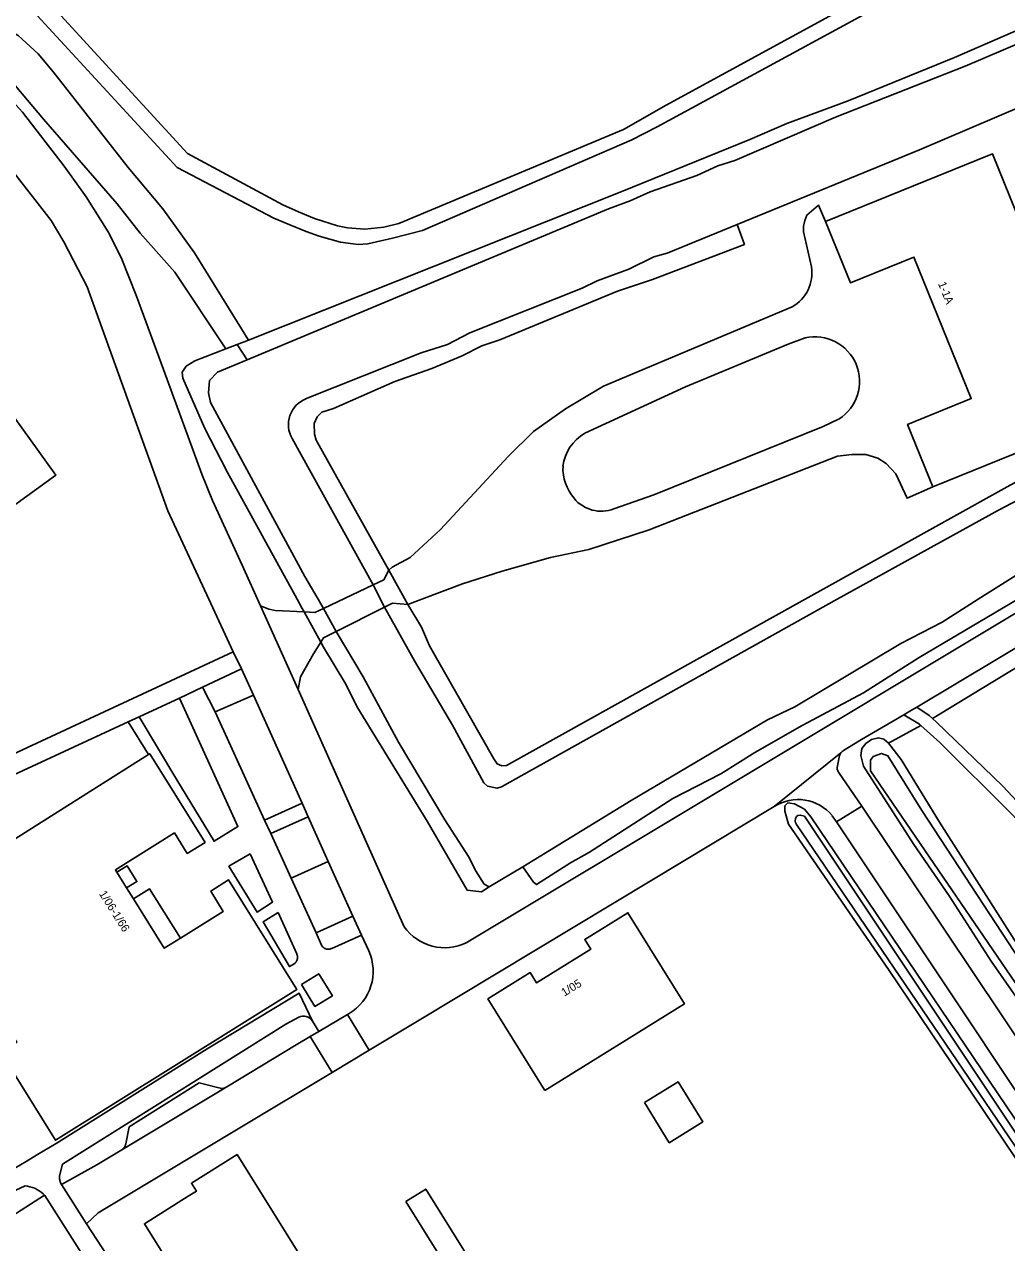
# Model space of a CAD drawing. Extents: x 162791 to 163827, y 385795 to 386523.
# Drawn here: x 163143.1 to 163263.1, y 386171.4 to 386320.2 of the extents above; entities that cross this region are included whole.
import ezdxf

# ---------------------------------------------------------------- set-up
doc = ezdxf.new("R2010")
doc.units = 0
for name, color, linetype in [('IMGEO_Dek', 7, 'Continuous'), ('IMGEO_Duiker', 7, 'Continuous'), ('IMGEO_Erf', 7, 'Continuous'), ('IMGEO_Gemengd_bos', 7, 'Continuous'), ('IMGEO_Groenvoorziening', 7, 'Continuous'), ('IMGEO_Pand', 7, 'Continuous'), ('IMGEO_Pand_nummerreeks', 7, 'Continuous'), ('IMGEO_Parkeervlak_halfverhard', 7, 'Continuous'), ('IMGEO_Parkeervlak_open', 7, 'Continuous'), ('IMGEO_Rijbaan_lokaal_gesloten', 7, 'Continuous'), ('IMGEO_Rijbaan_lokaal_onverhard', 7, 'Continuous'), ('IMGEO_Rijbaan_lokaal_open', 7, 'Continuous'), ('IMGEO_Voetpad_halfverhard', 7, 'Continuous'), ('IMGEO_Voetpad_open', 7, 'Continuous'), ('IMGEO_Waterloop', 7, 'Continuous'), ('IMGEO_Woonerf_gesloten', 7, 'Continuous'), ('IMGEO_Woonerf_open', 7, 'Continuous')]:
    doc.layers.add(name, color=color, linetype=linetype)

msp = doc.modelspace()

# ---------------------------------------------------------------- linework, layer by layer
at = {"layer": 'IMGEO_Dek'}
msp.add_lwpolyline([(163187.14, 386249.05), (163188.1, 386249.52), (163189.98, 386249.35), (163187.66, 386253.56), (163187.03, 386252.37), (163185.76, 386251.76), (163179.68, 386248.88), (163178.62, 386248.38), (163177.3, 386248.45), (163179.35, 386244.77), (163179.68, 386245.3), (163181.21, 386246.07)], close=True, dxfattribs=at)
at = {"layer": 'IMGEO_Duiker'}
msp.add_lwpolyline([(163170.35, 386279.25), (163169.11, 386281.15)], dxfattribs=at)
at = {"layer": 'IMGEO_Erf'}
for points in [[(163276.83, 386311.46), (163279.76, 386304.64), (163280.52, 386303.16), (163282.08, 386299.04), (163282.71, 386297.57), (163284.13, 386298.22), (163285.26, 386295.57), (163283.84, 386294.94), (163285.21, 386290.76), (163289.29, 386279.83), (163289.57, 386278.55), (163289.29, 386277.99), (163288.89, 386277.59), (163278.14, 386271.64), (163263.57, 386263.94), (163238.52, 386250), (163202.05, 386229.7), (163201.46, 386229.64), (163200.89, 386229.9), (163200.49, 386230.52), (163192.64, 386244.3), (163191.66, 386246.6), (163189.98, 386249.35)], [(163187.66, 386253.56), (163178.79, 386269.46), (163178.59, 386270.16), (163178.54, 386271.49), (163178.89, 386272.28), (163179.47, 386272.86), (163180.89, 386273.3), (163188.38, 386276.6), (163192.89, 386278.2), (163196.61, 386279.76), (163199.02, 386280.98), (163201.22, 386281.72), (163215.6, 386287.65), (163219.88, 386289.08), (163231.11, 386293.35), (163230.21, 386295.8)], [(163274.97, 386170.16), (163270.07, 386177.82), (163239.23, 386223.44), (163238.43, 386224.34), (163237.21, 386225.02), (163236.42, 386225.12), (163236.06, 386224.76), (163236.06, 386224.12), (163236.48, 386222.54), (163248.69, 386204.78), (163271.93, 386170.32)]]:
    msp.add_lwpolyline(points, dxfattribs=at)
at = {"layer": 'IMGEO_Gemengd_bos'}
for points in [[(163170.49, 386281.68), (163216.12, 386299.84), (163231.77, 386306.19), (163236.27, 386308.14), (163243.77, 386310.9), (163256.76, 386316.2), (163271.03, 386322.39), (163280.17, 386325.68), (163281.39, 386325.8), (163282.19, 386325.7), (163283.21, 386325.04), (163284.71, 386323.26), (163285.49, 386321.88), (163292.27, 386304.07), (163292.55, 386303.03), (163292.44, 386302.04), (163292.58, 386301.71)], [(163177.3, 386248.45), (163177.07, 386248.86), (163176.45, 386250), (163167.9, 386265.59), (163165.18, 386270.87), (163162.48, 386277.01), (163162.4, 386277.75), (163162.9, 386278.49), (163163.94, 386279.15), (163167.75, 386280.62)], [(163254.1, 386235.44), (163285.45, 386254.48)], [(163248.69, 386232.43), (163252.67, 386234.58)], [(163325.04, 386213.73), (163315.3, 386205.22), (163293.77, 386185.98), (163287.15, 386179.57), (163285.99, 386178.87), (163285.43, 386178.77), (163284.59, 386179.47), (163283.61, 386180.97), (163277.41, 386189.09), (163272.42, 386195.99), (163268.06, 386202.41), (163264.06, 386208.45), (163254.95, 386222.79), (163250.27, 386230.43), (163248.69, 386232.43)]]:
    msp.add_lwpolyline(points, dxfattribs=at)
at = {"layer": 'IMGEO_Groenvoorziening'}
for points in [[(163204.03, 386217.31), (163205.33, 386215.45), (163205.69, 386215.15), (163209.85, 386217.82), (163212.19, 386219.1), (163222.34, 386225.65), (163228.24, 386228.66), (163232.38, 386231.28), (163238.16, 386234.59), (163245.67, 386238.59), (163252.47, 386242.88), (163264.5, 386250)], [(163179.35, 386244.77), (163179.69, 386244.16), (163182.41, 386239.63), (163183.73, 386236.89), (163192.32, 386222.89), (163197.24, 386214.45), (163198.97, 386214.25), (163199.93, 386214.86)], [(163267.36, 386197.05), (163261.24, 386205.77), (163256.12, 386213.77), (163251.79, 386220.05), (163245.65, 386229.61), (163245.31, 386230.91), (163245.45, 386231.77), (163245.93, 386232.37), (163246.63, 386232.85), (163247.47, 386233.07), (163248.13, 386232.93), (163248.69, 386232.43)]]:
    msp.add_lwpolyline(points, dxfattribs=at)
at = {"layer": 'IMGEO_Pand'}
for points in [[(163254.14, 386263.73), (163270.42, 386270.34), (163265.9, 386281.46), (163266.76, 386281.81), (163267.23, 386280.63), (163270.52, 386281.97), (163261.4, 386304.44), (163259.5, 386303.66), (163241.01, 386296.16)], [(163254.14, 386263.73), (163251.04, 386271.37), (163258.82, 386274.53), (163251.81, 386291.81), (163244.05, 386288.66), (163241.01, 386296.16)], [(163119.61, 386245.38), (163146.97, 386265.18), (163139.77, 386275.14)], [(163158.27, 386231.02), (163130.88, 386213.71), (163126.72, 386211.09)], [(163158.27, 386231.02), (163158.44, 386231.12), (163165.2, 386220.3), (163163.02, 386218.95), (163161.46, 386221.45), (163154.24, 386216.94), (163154.41, 386216.67)], [(163154.41, 386216.67), (163155.67, 386217.45), (163156.88, 386215.52), (163155.62, 386214.73)], [(163155.62, 386214.73), (163154.41, 386216.67)], [(163162.18, 386208.59), (163167.43, 386211.87), (163165.89, 386214.34), (163168.08, 386215.71), (163176.43, 386202.34), (163146.92, 386183.91), (163140.23, 386194.67), (163140.94, 386195.11), (163142.21, 386195.91), (163139.88, 386199.39), (163138.39, 386201.6), (163135.58, 386205.79), (163134.6, 386205.17), (163131.63, 386203.3)], [(163155.62, 386214.73), (163156.44, 386213.41)], [(163156.44, 386213.41), (163158.41, 386214.64), (163162.18, 386208.59)], [(163156.44, 386213.41), (163160.22, 386207.37), (163162.18, 386208.59)], [(163206.71, 386189.99), (163199.77, 386201.17), (163204.94, 386204.39), (163205.71, 386203.14), (163212.34, 386207.26), (163211.6, 386208.44), (163216.87, 386211.71), (163223.77, 386200.58), (163206.71, 386189.99)], [(163218.88, 386188.5), (163221.92, 386183.6), (163226.04, 386186.16), (163222.99, 386191.06), (163218.88, 386188.5)], [(163163.46, 386164.63), (163157.78, 386173.71), (163163.15, 386177.06), (163164.14, 386177.67), (163163.53, 386178.65), (163169.11, 386182.15), (163176.67, 386170.08)], [(163189.73, 386176.43), (163195.39, 386167.34), (163197.83, 386168.86), (163192.17, 386177.95), (163189.73, 386176.43)]]:
    msp.add_lwpolyline(points, dxfattribs=at)
at = {"layer": 'IMGEO_Parkeervlak_halfverhard'}
for points in [[(163171.11, 386238.28), (163166.42, 386236.25)], [(163177.05, 386225.08), (163171.11, 386238.28)], [(163180.25, 386217.97), (163177.79, 386223.44)]]:
    msp.add_lwpolyline(points, dxfattribs=at)
at = {"layer": 'IMGEO_Parkeervlak_open'}
for points in [[(163172.47, 386223.02), (163177.05, 386225.08)], [(163177.79, 386223.44), (163177.05, 386225.08)], [(163177.79, 386223.44), (163173.22, 386221.39)], [(163175.71, 386215.93), (163180.25, 386217.97)], [(163183.27, 386211.27), (163180.25, 386217.97)], [(163178.77, 386209.26), (163183.27, 386211.27)], [(163155.01, 386182.73), (163155.09, 386182.78), (163155.16, 386182.84), (163155.23, 386182.91), (163155.29, 386182.98), (163155.34, 386183.05), (163155.39, 386183.13), (163155.43, 386183.21), (163155.47, 386183.3), (163155.49, 386183.39), (163155.51, 386183.48), (163155.93, 386185.54), (163164.46, 386190.92), (163167.03, 386190.29), (163167.08, 386190.27), (163167.14, 386190.25), (163167.2, 386190.24), (163167.26, 386190.24), (163167.32, 386190.23), (163167.38, 386190.24), (163167.43, 386190.24), (163167.49, 386190.26), (163167.55, 386190.28), (163167.6, 386190.3), (163167.66, 386190.33)], [(163155.01, 386182.73), (163167.66, 386190.33)]]:
    msp.add_lwpolyline(points, dxfattribs=at)
at = {"layer": 'IMGEO_Rijbaan_lokaal_gesloten'}
for points in [[(163187.14, 386249.05), (163188.1, 386249.52), (163189.98, 386249.35), (163187.66, 386253.56), (163187.03, 386252.37), (163185.76, 386251.76), (163179.68, 386248.88), (163178.62, 386248.38), (163177.3, 386248.45), (163179.35, 386244.77), (163179.68, 386245.3), (163181.21, 386246.07), (163187.14, 386249.05)], [(163176.56, 386238.97), (163171.99, 386249.22)], [(163171.99, 386249.22), (163173.01, 386248.79), (163173.75, 386248.64), (163177.3, 386248.45)], [(163177.3, 386248.45), (163179.35, 386244.77)], [(163179.35, 386244.77), (163178.47, 386243.33), (163176.88, 386240.52), (163176.56, 386238.97)]]:
    msp.add_lwpolyline(points, dxfattribs=at)
at = {"layer": 'IMGEO_Rijbaan_lokaal_onverhard'}
for points in [[(163279.57, 386173.72), (163245.44, 386224.72)], [(163242.34, 386222.83), (163278.57, 386168.48)]]:
    msp.add_lwpolyline(points, dxfattribs=at)
at = {"layer": 'IMGEO_Rijbaan_lokaal_open'}
for points in [[(163234.75, 386224.68), (163242.9, 386231.24)], [(163242.71, 386230.9), (163242.46, 386229.64)], [(163242.6, 386228.88), (163245.44, 386224.72)], [(163241.83, 386223.56), (163242.34, 386222.83)], [(163245.44, 386224.72), (163242.34, 386222.83)]]:
    msp.add_lwpolyline(points, dxfattribs=at)
for centre, radius, start, end in [((163243.94, 386230.43), 1.31, 141.977, 159.3233), ((163243.4, 386229.42), 0.966, 166.8322, 214.3438), ((163237.66, 386220.15), 5.39, 39.3459, 122.6739)]:
    msp.add_arc(centre, radius, start, end, dxfattribs=at)
at = {"layer": 'IMGEO_Voetpad_halfverhard'}
for points in [[(163146.68, 386322.3), (163163.05, 386304.46), (163174.71, 386298.21), (163176.62, 386297.32), (163178.56, 386296.51), (163181.4, 386295.62), (163182.61, 386295.4), (163184.73, 386295.24), (163187.04, 386295.46), (163188.87, 386295.91), (163216.32, 386307.39), (163221.54, 386310.39), (163244.17, 386322.73), (163244.86, 386324.42), (163239.28, 386332.37), (163230.09, 386349.78), (163225.52, 386357.53), (163223.2, 386360.2)], [(163275.88, 386331.29), (163260.37, 386325.29), (163252.83, 386323.64), (163249.2, 386322.85), (163247.32, 386322.31), (163245.56, 386321.36), (163220.43, 386307.74), (163217.35, 386306.13), (163191.76, 386295.05), (163188.1, 386294.14), (163185.1, 386293.41), (163183.89, 386293.36), (163181.73, 386293.63), (163179.14, 386294.37), (163177.56, 386294.94), (163175.56, 386295.74), (163173.59, 386296.58), (163161.79, 386302.75), (163144.67, 386321.31)], [(163250.59, 386235.88), (163251.52, 386236.45), (163252.17, 386236.84)], [(163252.17, 386236.84), (163253.66, 386235.82), (163254.1, 386235.44)], [(163252.67, 386234.58), (163252.49, 386234.75), (163250.59, 386235.88)], [(163254.1, 386235.44), (163254.59, 386235), (163262.7, 386227.16), (163272.38, 386216.79), (163275.53, 386213.52), (163282.75, 386217.01), (163283.13, 386217.51)], [(163252.67, 386234.58), (163254.97, 386232.49), (163263.75, 386223.77), (163272.16, 386214.81), (163275.43, 386211.39), (163277.77, 386208.82), (163280.39, 386199.43), (163282.54, 386194.16), (163284.97, 386190.31), (163290.61, 386189.54), (163297.88, 386195.47), (163302.17, 386202.38)]]:
    msp.add_lwpolyline(points, dxfattribs=at)
at = {"layer": 'IMGEO_Voetpad_open'}
for points in [[(163241.01, 386296.16), (163240.14, 386298.17), (163238.75, 386296.92)], [(163238.47, 386294.19), (163239.31, 386290.62)], [(163236.95, 386285.72), (163213.9, 386276.05), (163209.26, 386273.27), (163205.34, 386270.51), (163202.25, 386267.46), (163193.97, 386258.51), (163190.27, 386255.1), (163188.07, 386253.92), (163187.66, 386253.56)], [(163238.51, 386281.93), (163236.46, 386281.19), (163223.91, 386275.96), (163211.61, 386270.29)], [(163215.15, 386261.04), (163220.05, 386262.77), (163240.72, 386271.13)], [(163240.72, 386271.13), (163242.62, 386272.01)], [(163189.98, 386249.35), (163191.7, 386250), (163196.64, 386251.88), (163201.52, 386253.45), (163207.4, 386255.09), (163212.11, 386256.1), (163219.47, 386258.48), (163242.46, 386267.47), (163244.24, 386267.69), (163245.94, 386267.69), (163247.4, 386267.25), (163248.43, 386266.59), (163249.59, 386265.31), (163250.99, 386262.35), (163254.14, 386263.73)], [(163189.98, 386249.35), (163187.66, 386253.56)], [(163164.89, 386239.25), (163162.07, 386237.92)], [(163166.42, 386236.25), (163164.89, 386239.25)], [(163162.07, 386237.92), (163169.22, 386222.24), (163166.3, 386220.43), (163161.77, 386227.95), (163157.13, 386235.63)], [(163157.13, 386235.63), (163155.82, 386235.03)], [(163166.42, 386236.25), (163172.47, 386223.02)], [(163155.82, 386235.03), (163158.27, 386231.02)], [(163172.47, 386223.02), (163173.22, 386221.39)], [(163173.22, 386221.39), (163175.71, 386215.93)], [(163170.73, 386218.9), (163173.43, 386212.99), (163171.55, 386211.78), (163168.11, 386217.38), (163170.73, 386218.9)], [(163175.71, 386215.93), (163178.77, 386209.26)], [(163174.14, 386211.73), (163176.4, 386206.68), (163176.43, 386206.6), (163176.46, 386206.52), (163176.48, 386206.44), (163176.49, 386206.35), (163176.5, 386206.27), (163176.5, 386206.18), (163176.49, 386206.1), (163176.47, 386206.01), (163176.44, 386205.93), (163176.41, 386205.85), (163176.37, 386205.78), (163176.33, 386205.7), (163176.27, 386205.63), (163176.21, 386205.57), (163176.15, 386205.51), (163175.51, 386205.13), (163172.3, 386210.61), (163174.14, 386211.73)], [(163184.32, 386208.97), (163180.67, 386207.35), (163180.59, 386207.32), (163180.52, 386207.29), (163180.44, 386207.27), (163180.36, 386207.26), (163180.28, 386207.25), (163180.2, 386207.25), (163180.12, 386207.26), (163180.04, 386207.27), (163179.96, 386207.29), (163179.89, 386207.32), (163179.82, 386207.35), (163179.75, 386207.39), (163179.68, 386207.44), (163179.62, 386207.49), (163179.56, 386207.55), (163179.51, 386207.61), (163179.46, 386207.67), (163179.42, 386207.74), (163178.77, 386209.26)], [(163184.32, 386208.97), (163185.2, 386207.04)], [(163176.97, 386202.93), (163179.1, 386204.24), (163180.76, 386201.56), (163178.63, 386200.25), (163176.97, 386202.93)], [(163137, 386178.43), (163138.64, 386178.99), (163141.28, 386180.1), (163143.33, 386181.33), (163144.74, 386182.18), (163147, 386183.52), (163165.46, 386195.06), (163176.71, 386201.87), (163178.31, 386198.47)], [(163178.31, 386198.47), (163179.09, 386197.18)], [(163182.62, 386199.28), (163179.09, 386197.18)], [(163182.8, 386199.39), (163182.62, 386199.28)]]:
    msp.add_lwpolyline(points, dxfattribs=at)
for centre, radius, start, end in [((163241.94, 386295.22), 3.62, 151.952, 196.4106), ((163234.54, 386289.9), 4.82, 299.9764, 8.5727), ((163239.72, 386276.62), 5.45, 302.1781, 102.9032), ((163214.22, 386265.65), 5.32, 119.4185, 173.4513), ((163214.33, 386265.94), 5.4, 176.5722, 221.7042), ((163213.64, 386265.1), 4.34, 219.5286, 290.4148), ((163179.74, 386204.55), 6, 300.7437, 24.5124)]:
    msp.add_arc(centre, radius, start, end, dxfattribs=at)
at = {"layer": 'IMGEO_Waterloop'}
for points in [[(163199.93, 386214.86), (163199.31, 386215.21), (163198.26, 386216.85), (163197.46, 386218.47), (163194.48, 386223.05), (163188.82, 386232.55), (163184.51, 386240.51), (163181.21, 386246.07), (163179.68, 386248.88), (163179.02, 386250), (163177.39, 386252.77), (163165.86, 386274.05), (163165.6, 386275.21), (163165.76, 386276.73), (163166.7, 386277.73), (163170.35, 386279.25), (163214.5, 386297.72), (163217.14, 386298.68), (163219.6, 386299.78), (163225.3, 386301.79), (163227.87, 386302.95), (163229.95, 386303.61), (163242.23, 386308.92), (163258.08, 386315.12), (163269.93, 386320.19)], [(163167.75, 386280.62), (163161.49, 386289.96), (163157.29, 386294.73), (163154.47, 386298.31), (163145.44, 386308.65), (163140.02, 386315.11), (163139.62, 386316.27), (163139.8, 386318.11), (163140.18, 386318.76), (163141.64, 386319.29), (163142.36, 386318.89), (163144.8, 386316.64), (163146.68, 386314.42), (163155.79, 386302.74), (163160.03, 386297.72), (163163.89, 386292.32), (163170.49, 386281.68)], [(163230.21, 386295.8), (163252.5, 386304.93), (163271.39, 386312.98)], [(163230.21, 386295.8), (163221.65, 386292.3), (163220.02, 386291.86), (163216.98, 386290.34), (163213.1, 386288.91), (163211.26, 386288.03), (163197.57, 386282.54), (163194.83, 386281.12), (163191.59, 386280.13), (163177.49, 386274.48)], [(163170.49, 386281.68), (163169.11, 386281.15), (163167.75, 386280.62)], [(163175.83, 386269.65), (163185.76, 386251.76), (163187.14, 386249.05), (163190.78, 386242.48), (163195.42, 386234.62), (163199.28, 386227.57), (163199.7, 386227.18), (163200.88, 386226.92), (163201.42, 386227.1), (163242.44, 386250), (163262.13, 386260.88), (163269.34, 386264.69)], [(163264.7, 386253.2), (163259.65, 386250), (163255.25, 386247.21), (163250.23, 386244.61), (163237.26, 386236.87), (163233.94, 386235.26), (163217.27, 386225.41), (163204.03, 386217.31)], [(163282.46, 386176.42), (163246.5, 386229.06), (163246.53, 386230.33), (163246.84, 386230.78), (163247.84, 386231.17), (163248.64, 386230.86), (163252.8, 386224.21), (163282.93, 386178.18)], [(163237.48, 386222.5), (163237.35, 386222.72), (163237.3, 386222.9), (163237.35, 386223.22), (163237.48, 386223.45), (163237.62, 386223.57), (163237.92, 386223.64), (163238.44, 386223.52), (163275.25, 386168.27), (163275.18, 386166.43), (163274.92, 386166.02), (163274.67, 386165.69), (163273.71, 386164.82), (163272.34, 386163.57), (163235.78, 386130.19), (163234.78, 386129.26), (163230.58, 386125.39), (163228.62, 386123.58)], [(163227.42, 386124.6), (163230.07, 386127.03), (163230.82, 386127.65), (163233.56, 386130.11), (163233.95, 386130.45), (163240.94, 386136.66), (163273.9, 386166.17), (163274.36, 386166.68), (163274.54, 386167.36), (163274.4, 386168.21), (163273.87, 386168.93), (163237.48, 386222.5)], [(163199.93, 386214.86), (163204.03, 386217.31)]]:
    msp.add_lwpolyline(points, dxfattribs=at)
msp.add_arc((163178.75, 386271.35), 3.37, 111.8018, 210.2063, dxfattribs=at)
at = {"layer": 'IMGEO_Woonerf_gesloten'}
for points in [[(163109.74, 386223.18), (163108.77, 386224.5), (163112.01, 386226.56), (163121.38, 386213.38), (163121.39, 386213.52), (163121.74, 386215.48), (163122.28, 386217.14), (163123.04, 386218.53), (163123.91, 386219.7), (163125.04, 386221.15), (163126.28, 386222.51), (163127.63, 386223.76), (163129.08, 386224.9), (163130.61, 386225.91), (163168.65, 386243.58)], [(163168.65, 386243.58), (163169.67, 386241.49)], [(163164.89, 386239.25), (163169.67, 386241.49)], [(163157.13, 386235.63), (163162.07, 386237.92)], [(163123.86, 386209.28), (163123.81, 386209.56), (163123.73, 386210.74), (163123.75, 386211.92), (163123.87, 386213.1), (163124.09, 386214.26), (163124.41, 386215.4), (163125.01, 386216.7), (163125.72, 386217.95), (163126.53, 386219.13), (163127.43, 386220.24), (163128.43, 386221.27), (163129.8, 386222.6), (163130.49, 386223.11), (163132.74, 386224.35), (163136.27, 386225.97), (163155.82, 386235.03)], [(163176.65, 386198.93), (163175.05, 386198.08), (163147.8, 386180.97), (163147.42, 386179.56), (163147.41, 386179.45), (163147.41, 386179.33), (163147.42, 386179.21), (163147.44, 386179.09), (163147.46, 386178.97), (163147.49, 386178.85), (163147.54, 386178.73), (163147.58, 386178.62), (163147.64, 386178.51)], [(163145.58, 386177.19), (163145.4, 386177.37), (163145.17, 386177.57), (163144.92, 386177.74), (163144.66, 386177.9), (163144.39, 386178.04), (163144.1, 386178.15), (163143.8, 386178.23), (163143.51, 386178.29), (163143.2, 386178.32), (163140.39, 386177.04), (163138.14, 386176.08)], [(163150.73, 386173.68), (163147.64, 386178.51)], [(163145.58, 386177.19), (163145.62, 386177.15), (163149.82, 386170.54), (163149.98, 386170.29)], [(163150.73, 386173.68), (163160.14, 386159.28), (163167.48, 386147.99), (163174, 386137.85), (163187.42, 386117.38), (163196.41, 386103.58), (163197.55, 386102.2)]]:
    msp.add_lwpolyline(points, dxfattribs=at)
msp.add_arc((163177.24, 386197.82), 1.25, 31.3518, 117.8506, dxfattribs=at)
at = {"layer": 'IMGEO_Woonerf_open'}
for points in [[(163125.21, 386315.3), (163126.92, 386314.28), (163134.86, 386309.61), (163137.48, 386307.69), (163146.39, 386296.27), (163147.95, 386293.69), (163150.79, 386288.19), (163160.64, 386260.8), (163165.66, 386250), (163168.65, 386243.58)], [(163171.99, 386249.22), (163169.72, 386254.16), (163166.11, 386262.07), (163164.81, 386265.29), (163160.14, 386278.08), (163156.81, 386287.04), (163154.95, 386291.78), (163153.35, 386294.91), (163150.68, 386299.19), (163148, 386302.92), (163142.88, 386309.51), (163141.21, 386311.35), (163138.51, 386313.4), (163137.92, 386313.88), (163137.36, 386314.41), (163136.86, 386314.98)], [(163301.9, 386270.89), (163227.75, 386226.41), (163197.1, 386208.03), (163196.61, 386207.82), (163196.11, 386207.65), (163195.59, 386207.53), (163195.06, 386207.46), (163194.53, 386207.43), (163194, 386207.45), (163193.48, 386207.51), (163192.96, 386207.62), (163192.45, 386207.78), (163191.96, 386207.98), (163191.49, 386208.22), (163191.04, 386208.5), (163190.62, 386208.82), (163190.23, 386209.18), (163189.87, 386209.57), (163189.54, 386209.99), (163176.56, 386238.97)], [(163252.17, 386236.84), (163267.08, 386245.73), (163282.9, 386255.22)], [(163169.67, 386241.49), (163171.11, 386238.28)], [(163243.2, 386231.52), (163245.4, 386232.86), (163250.59, 386235.88)], [(163185.27, 386194.92), (163191.37, 386198.58), (163219.8, 386215.69), (163234.75, 386224.68)], [(163183.27, 386211.27), (163184.32, 386208.97)], [(163185.27, 386194.92), (163182.62, 386199.28)], [(163179.09, 386197.18), (163178.06, 386196.57)], [(163167.66, 386190.33), (163167.71, 386190.36), (163167.87, 386190.45), (163176.34, 386195.55), (163178.06, 386196.57)], [(163178.06, 386196.57), (163180.73, 386192.18)], [(163180.73, 386192.18), (163185.27, 386194.92)], [(163180.73, 386192.18), (163176.05, 386189.37), (163174.35, 386188.35), (163152.12, 386175.02), (163150.73, 386173.68)], [(163147.64, 386178.51), (163151.96, 386180.91), (163155.01, 386182.73)], [(163139.83, 386173.53), (163145.58, 386177.19)]]:
    msp.add_lwpolyline(points, dxfattribs=at)
msp.add_arc((163243.89, 386230.46), 1.26, 123.2143, 141.8238, dxfattribs=at)

# ---------------------------------------------------------------- texts
at = {"layer": 'IMGEO_Pand_nummerreeks'}
for s, rotation, p in [('1-1A', 292.0988, (163254.74, 386288.57)), ('1/06-1/66', 302.2917, (163152.2, 386214.03)), ('1/05', 31.5002, (163209.1, 386201.44))]:
    msp.add_text(s, height=1, rotation=rotation, dxfattribs=at).set_placement(p)

doc.saveas('drawing.dxf')
